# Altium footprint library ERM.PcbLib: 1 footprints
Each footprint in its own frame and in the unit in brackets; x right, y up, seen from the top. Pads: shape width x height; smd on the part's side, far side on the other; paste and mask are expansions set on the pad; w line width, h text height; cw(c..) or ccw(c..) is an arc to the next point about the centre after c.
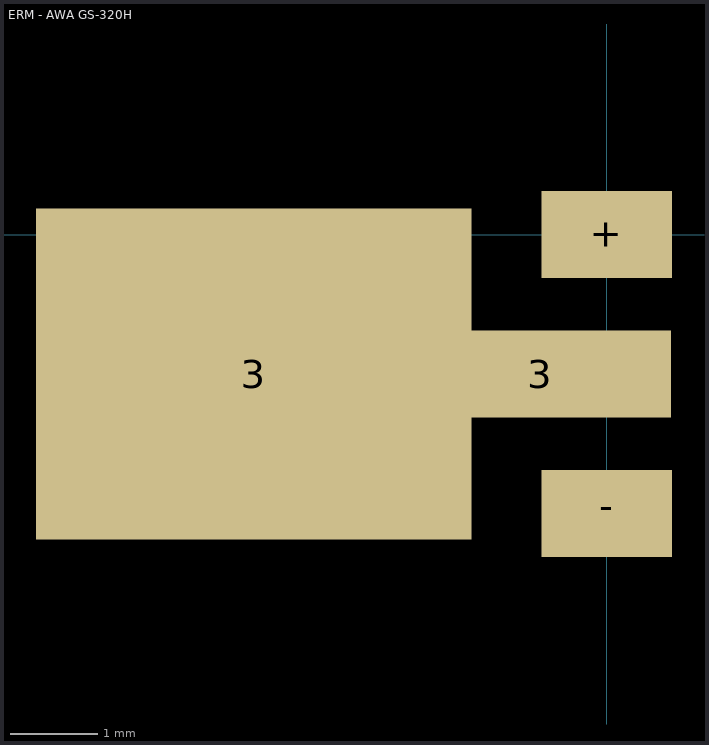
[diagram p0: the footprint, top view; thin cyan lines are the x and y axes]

## ERM - AWA GS-320H [mm] "ERM Actuator"
pads (4):
  rect 5x3.8 smd: 3(-4.05,-1.6)
  rect 3x1 smd: 3(-0.762,-1.6)
  rect 1.5x1 smd: +(0,0) -(0,-3.2)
